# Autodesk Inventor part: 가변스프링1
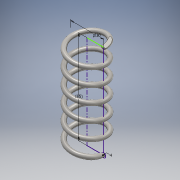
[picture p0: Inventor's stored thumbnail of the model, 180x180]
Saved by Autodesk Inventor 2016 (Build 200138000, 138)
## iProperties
Created: 2017-03
Part Number: 가변스프링1
Material: 강철, 탄소
Document SubType Name: Modeling
Designer: USER
Mass: 55.2215 g
Surface Area: 71.3448 cm^2
Volume: 7.03459 cm^3
Density: 7.85 g/cm^3
Appearance: 반연마
Author: USER
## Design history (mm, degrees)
sketch "스케치1"
  geometry: L1 (0, 0)-(-15, 0); L2 (-15, 0)-(-15, 84.368); L3 (-15, 84.368)-(0, 84.368); L4 (0, 84.368)-(0, 0); C1 r 2 at (-15, 0)
  constraints: 8 end point, 2 parallel, 1 centre point, 1 coincident, 1 horizontal, 1 perpendicular
  dimensions: "d0" = 4 diameter of C1; "d1" = 30 diameter of L2 L4; "d2" = 84.36759 distance between parallel lines of L1 L3 (derived)
feature "코일1" pitch "d3" = 10; turns "d5" = 6; dims "d4" = 84.36759 (= d2), "d6" = 0, angle "d7" = 90 deg, angle "d8" = 90 deg, "d9" = 0, "d10" = 0
sketch "스케치2"
  geometry: L1 (13, 0)-(17, 0) reference; 1 further point
  constraints: 1 horizontal alignment
extrude "돌출1" cut sketch "스케치2" stored distance "d11" = 10; taper "d12" = 0 deg
node "작업 평면1"
sketch "스케치3"
  geometry: L1 (-13, 0)-(-17, 0) reference; 1 further point
  constraints: 1 horizontal alignment
extrude "돌출2" cut sketch "스케치3" stored distance "d13" = 10; taper "d14" = 0 deg
node "솔리드1"
node "절단 모서리 투영1"
node "절단 모서리 투영2"
